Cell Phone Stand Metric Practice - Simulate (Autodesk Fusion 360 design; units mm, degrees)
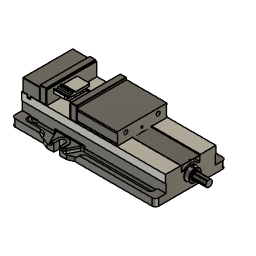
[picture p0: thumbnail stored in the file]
description: HaasClamp
derived_base_feature "Derived Base Feature" bodies "Stand Body"
align "Align1"
base_feature "Base Feature1"
base_feature "Base Feature1"
base_feature "Base Feature1"
base_feature "Base Feature1"
base_feature "Base Feature1"
base_feature "Base Feature1"
base_feature "Base Feature1"
base_feature "Base Feature1"
base_feature "Base Feature1"
base_feature "Base Feature1"
as_built_joint "As-built1"
as_built_joint "As-built2"
as_built_joint "As-built3"
joint_origin "JointOrigin1" OffsetX 0 OffsetY 0 OffsetZ 0 AngleZ 0
joint "Assemble1" alignAngle 180 alignOffsetX 0 alignOffsetY 0 alignOffsetZ 0 (= "jaw_width_haas_050002") SlideMaximum 22.5 SlideMinimum 0
position "Position1"
sketch "Sketch1" plane through (0, -72.5, 0) normal (0, -1, 0) x axis (1, 0, 0)
  line L1 (75, 73) -> (-75, 73)
  line L2 (76, 74) -> (75, 73)
  line L3 (76, 116.5) -> (76, 74)
  line L4 (75, 117.5) -> (76, 116.5)
  line L5 (-75, 117.5) -> (75, 117.5)
  line L6 (-76, 116.5) -> (-75, 117.5)
  line L7 (-76, 74) -> (-76, 116.5)
  line L8 (-75, 73) -> (-76, 74)
  line L9 (76.4, 114.275) -> (-76, 114.275)
  line L10 (76.4, 73) -> (76.4, 114.275)
  line L11 (-76, 73) -> (76.4, 73)
  line L12 (-76, 114.275) -> (-76, 73)
  circle C1 centre (49.21, 96.8) radius 11
  circle C2 centre (-49.21, 96.8) radius 11
  point P14 (76.4, 73)
  point P12 (-76, 114.275)
  point P13 (76.4, 114.275)
  horizontal L9
  vertical L10
  horizontal L11
  vertical L12
  coincident L1 P14
  coincident L7 P12
  dimension "d16" distance P12 P13 = 152.4
  dimension "d17" distance P13 P14 = 41.275
place_component sketch "Sketch1"
extrude "Extrude1" new body sketch "Sketch1" profile of L1 L2 L3 L7 L8 C1 C2 L9 L11 L12 along normal blind 3.175
place_component sketch "Sketch1"
extrude "Extrude1" sketch "Sketch1" profile of L1 L2 L3 L7 L8 C1 C2 L9 L11 L12 blind -3.175
as_built_joint "As-built5"
as_built_joint "As-built6"
sketch "Sketch1" plane through (0, 0, 0) normal (0, 0, -1) x axis (1, 0, 0)
  line L1 (16.5, -37.5) -> (-16.5, -37.5)
  line L2 (20, 34) -> (20, -34)
  line L3 (-16.5, 37.5) -> (16.5, 37.5)
  line L4 (-20, -34) -> (-20, 34)
  line L5 (-38.1, -40) -> (38.1, -40)
  line L6 (-38.1, 40) -> (-38.1, -40)
  line L7 (38.1, 40) -> (-38.1, 40)
  line L8 (38.1, -40) -> (38.1, 40)
  line L9 (-38.1, 40) -> (38.1, -40)
  line L10 (38.1, 40) -> (-38.1, -40)
  arc A1 centre (-16.5, -34) radius 3.5 clockwise from (-16.5, -37.5) to (-20, -34)
  arc A2 centre (16.5, -34) radius 3.5 clockwise from (20, -34) to (16.5, -37.5)
  arc A3 centre (16.5, 34) radius 3.5 clockwise from (16.5, 37.5) to (20, 34)
  arc A4 centre (-16.5, 34) radius 3.5 clockwise from (-20, 34) to (-16.5, 37.5)
  point P18 (0, 0)
  point P1 (0, 0)
  point P16 (-38.1, 40)
  point P17 (38.1, 40)
  point P15 (-38.1, -40)
  horizontal L5
  perpendicular L5 L6
  parallel L5 L7
  parallel L6 L8
  coincident L9 P18
  coincident L10 P18
  coincident P1 P18
  dimension "d1" distance P16 P17 = 76.2
  dimension "d2" distance P15 P16 = 80
extrude "Extrude1" new body sketch "Sketch1" profile of A1 L1 A2 L2 A3 L3 A4 L4 L5 L6 L7 L8 against normal blind 10 bodies "Stock"
position "Position1"
ground "Pin"
position "Position2"
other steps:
create_component "CreateComponent1"
create_component "CreateComponent2"
create_component "CreateComponent3"
create_component "CreateComponent4"
create_component "CreateComponent5"
create_component "CreateComponent6"
create_component "CreateComponent7"
create_component "CreateComponent8"
create_component "CreateComponent9"
create_component "CreateComponent10"
joint_origin "JointOrigin10"
joint_origin "JointOrigin11"
create_component "CreateComponent11" sketch "Sketch1"
create_component "CreateComponent12" sketch "Sketch1"
create_component "CreateComponent1"
named bodies: "Stand Body", "Stock"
